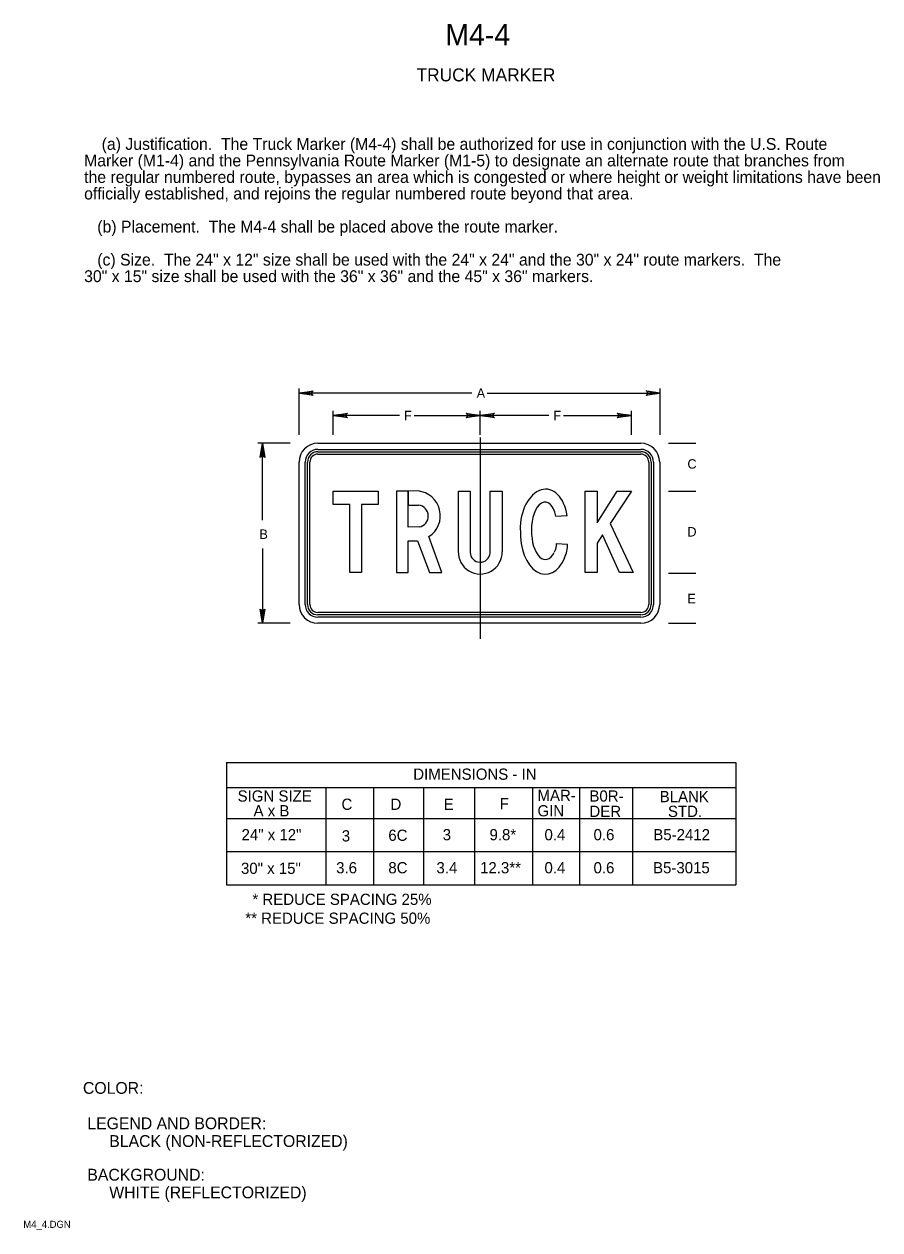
# Model space of a CAD drawing. Extents: x 0.013 to 0.194, y 0.004 to 0.259.
import ezdxf

# ---------------------------------------------------------------- set-up
doc = ezdxf.new("R2010")
doc.units = 0
for name, color, linetype in [('1', 7, 'Continuous'), ('2', 7, 'Continuous'), ('3', 7, 'Continuous')]:
    doc.layers.add(name, color=color, linetype=linetype)

# ---------------------------------------------------------------- blocks, each defined once
blk = doc.blocks.new('RARROW')
at = {"layer": '3'}
for p, q in [((-2.156, 0.28500000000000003), (-2.2665, 0.384625)), ((-2.2665, 0.384625), (0, 0)), ((0, 0), (-2.2665, -0.379125)), ((-2.156, 0.28500000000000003), (-2.075625, 0.12075)), ((0, 0), (-2.156, 0.28500000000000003)), ((-2.14975, -0.2705), (0, 0)), ((-2.075625, 0.12075), (0, 0)), ((0, 0), (-2.074, -0.108)), ((-2.2665, -0.379125), (-2.14975, -0.2705)), ((-2.074, -0.108), (-2.14975, -0.2705))]:
    blk.add_line(p, q, dxfattribs=at)

msp = doc.modelspace()

# ---------------------------------------------------------------- linework, layer by layer
at = {"layer": '2'}
for p, q in [((0.074875, 0.1705), (0.14325000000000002, 0.1705)), ((0.07087500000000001, 0.136375), (0.07087500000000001, 0.1665)), ((0.14725, 0.1665), (0.14725, 0.136375)), ((0.104625, 0.160375), (0.107125, 0.160375)), ((0.104625, 0.147625), (0.104625, 0.160375)), ((0.107125, 0.160375), (0.107125, 0.147375)), ((0.111375, 0.14725), (0.111375, 0.160375)), ((0.111375, 0.160375), (0.113875, 0.160375)), ((0.113875, 0.160375), (0.113875, 0.1475)), ((0.14325000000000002, 0.132375), (0.074875, 0.132375))]:
    msp.add_line(p, q, dxfattribs=at)
for points in [[(0.078125, 0.160375), (0.08762500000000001, 0.160375), (0.08762500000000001, 0.1575), (0.084125, 0.1575), (0.084125, 0.143125), (0.081625, 0.143125), (0.081625, 0.1575), (0.078125, 0.1575), (0.078125, 0.160375)], [(0.1315, 0.143125), (0.1315, 0.160375), (0.134, 0.160375), (0.134, 0.153625), (0.13825, 0.160375), (0.14125000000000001, 0.160375), (0.13675, 0.1535), (0.141625, 0.143125), (0.13875, 0.143125), (0.135125, 0.151125), (0.134, 0.149375), (0.134, 0.143125), (0.1315, 0.143125)]]:
    msp.add_lwpolyline(points, dxfattribs=at)
for centre, radius, start, end in [((0.074875, 0.1665), 0.004, 90, 180), ((0.14325000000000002, 0.1665), 0.004, 0, 90), ((0.1092502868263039, 0.14746159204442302), 0.004645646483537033, 177.67846944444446, 0.7742194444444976), ((0.1092502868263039, 0.14746159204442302), 0.0021456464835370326, 181.68468333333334, 355.2363583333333), ((0.074875, 0.136375), 0.004, 180, 270), ((0.14325000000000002, 0.136375), 0.004, 270, 0)]:
    msp.add_arc(centre, radius, start, end, dxfattribs=at)
at = {"layer": '3'}
for p, q in [((0.07087500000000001, 0.17225000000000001), (0.07087500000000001, 0.182125)), ((0.147375, 0.17225000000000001), (0.147375, 0.182125)), ((0.1075, 0.181125), (0.07087500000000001, 0.181125)), ((0.11075, 0.181125), (0.147375, 0.181125)), ((0.078125, 0.17225000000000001), (0.078125, 0.177375)), ((0.092125, 0.176375), (0.078125, 0.176375)), ((0.09525, 0.176375), (0.10925, 0.176375)), ((0.10925, 0.17225000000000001), (0.10925, 0.177375)), ((0.12375, 0.176375), (0.10925, 0.176375)), ((0.12687500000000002, 0.176375), (0.14125000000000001, 0.176375)), ((0.14125000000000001, 0.17225000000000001), (0.14125000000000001, 0.177375)), ((0.10925, 0.17175), (0.10925, 0.129125)), ((0.069, 0.1705), (0.062125, 0.1705)), ((0.063125, 0.15425), (0.063125, 0.1705)), ((0.074875, 0.16919999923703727), (0.14325000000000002, 0.16919999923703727)), ((0.074875, 0.16869999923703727), (0.14325000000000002, 0.16869999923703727)), ((0.149125, 0.1705), (0.154875, 0.1705)), ((0.07217500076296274, 0.136375), (0.07217500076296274, 0.1665)), ((0.07267500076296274, 0.136375), (0.07267500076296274, 0.1665)), ((0.07317500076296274, 0.136375), (0.07317500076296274, 0.1665)), ((0.074875, 0.16819999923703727), (0.14325000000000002, 0.16819999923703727)), ((0.14494999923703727, 0.1665), (0.14494999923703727, 0.136375)), ((0.14544999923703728, 0.1665), (0.14544999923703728, 0.136375)), ((0.14594999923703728, 0.1665), (0.14594999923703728, 0.136375)), ((0.094, 0.160375), (0.0915, 0.160375)), ((0.0915, 0.160375), (0.0915, 0.143125)), ((0.09607265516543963, 0.16039909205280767), (0.094, 0.160375)), ((0.094, 0.160375), (0.094, 0.15737500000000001)), ((0.094, 0.15737500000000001), (0.094, 0.160375)), ((0.149125, 0.160375), (0.154875, 0.160375)), ((0.094, 0.15737500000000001), (0.09620825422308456, 0.15739909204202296)), ((0.094, 0.15275), (0.094, 0.15737500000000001)), ((0.12762500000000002, 0.155125), (0.12525, 0.155)), ((0.12762500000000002, 0.155125), (0.12762500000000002, 0.155125)), ((0.09633325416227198, 0.15277409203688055), (0.094, 0.15275)), ((0.101125, 0.143125), (0.09839251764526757, 0.15073655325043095)), ((0.063125, 0.14825), (0.063125, 0.132375)), ((0.094, 0.143125), (0.094, 0.149875)), ((0.094, 0.149875), (0.096, 0.149875)), ((0.096, 0.149875), (0.0985, 0.143125)), ((0.12537500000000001, 0.14925), (0.12775, 0.149125)), ((0.0915, 0.143125), (0.094, 0.143125)), ((0.0985, 0.143125), (0.101125, 0.143125)), ((0.149125, 0.14300000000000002), (0.154875, 0.14300000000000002)), ((0.14325000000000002, 0.13467500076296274), (0.074875, 0.13467500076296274)), ((0.14325000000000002, 0.13417500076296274), (0.074875, 0.13417500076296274)), ((0.14325000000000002, 0.13367500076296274), (0.074875, 0.13367500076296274)), ((0.069, 0.132375), (0.062125, 0.132375)), ((0.149125, 0.132375), (0.154875, 0.132375)), ((0.0555, 0.10300000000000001), (0.0555, 0.077)), ((0.05556501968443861, 0.10293729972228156), (0.16334630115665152, 0.10293729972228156)), ((0.16334630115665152, 0.10293729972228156), (0.16334630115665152, 0.07697560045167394)), ((0.16334630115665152, 0.09757560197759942), (0.05556501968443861, 0.09757560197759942)), ((0.07652585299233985, 0.09757560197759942), (0.07652585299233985, 0.07697560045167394)), ((0.08662654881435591, 0.09757560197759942), (0.08662654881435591, 0.07697560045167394)), ((0.09726460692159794, 0.09757560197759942), (0.09726460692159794, 0.07697560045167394)), ((0.10800620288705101, 0.09757560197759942), (0.10800620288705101, 0.07697560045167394)), ((0.12031398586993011, 0.09763013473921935), (0.12031398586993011, 0.07703013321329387)), ((0.1302917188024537, 0.09757560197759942), (0.1302917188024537, 0.07697560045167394)), ((0.14150099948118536, 0.09757560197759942), (0.14150099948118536, 0.07697560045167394)), ((0.05556501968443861, 0.09107560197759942), (0.16334630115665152, 0.09107560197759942)), ((0.05556501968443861, 0.08407560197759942), (0.16334630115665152, 0.08407560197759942)), ((0.05552343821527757, 0.07697560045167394), (0.16334630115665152, 0.07697560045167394))]:
    msp.add_line(p, q, dxfattribs=at)
for centre, radius, start, end in [((0.074875, 0.1665), 0.0027, 90, 180), ((0.074875, 0.1665), 0.0022, 90, 180), ((0.14325000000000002, 0.1665), 0.0027, 0, 90), ((0.14325000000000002, 0.1665), 0.0022, 0, 90), ((0.074875, 0.1665), 0.0017000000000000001, 90, 180), ((0.14325000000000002, 0.1665), 0.0017000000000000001, 0, 90), ((0.0955364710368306, 0.15516060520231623), 0.005265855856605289, 302.8451777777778, 84.15585555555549), ((0.09591677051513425, 0.1550770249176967), 0.002340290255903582, 280.25109722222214, 82.84521666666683), ((0.12256278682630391, 0.14896159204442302), 0.002829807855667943, 329.47029444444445, 6.340191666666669), ((0.12030352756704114, 0.14926251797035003), 0.007447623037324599, 336.34308888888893, 359.12736111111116), ((0.074875, 0.136375), 0.0027, 180, 270), ((0.074875, 0.136375), 0.0022, 180, 270), ((0.074875, 0.136375), 0.0017000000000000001, 180, 270), ((0.14325000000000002, 0.136375), 0.0027, 270, 0), ((0.14325000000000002, 0.136375), 0.0017000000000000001, 270, 0), ((0.14325000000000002, 0.136375), 0.0022, 270, 0)]:
    msp.add_arc(centre, radius, start, end, dxfattribs=at)
for centre, major_axis, ratio, start_param, end_param in [((0.12275028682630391, 0.152899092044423), (0.0005900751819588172, 0.007867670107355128), 0.6355121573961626, 5.051914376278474, 8.000065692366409), ((0.12275028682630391, 0.15296159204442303), (0.0003616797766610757, 0.005063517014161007), 0.5184143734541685, 5.18183954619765, 8.061923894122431), ((0.12287528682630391, 0.151086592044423), (-0.000304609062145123, 0.008325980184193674), 0.6155431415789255, 1.4327922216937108, 4.066766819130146), ((0.12293778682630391, 0.151586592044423), (-0.0001270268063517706, 0.0057162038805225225), 0.4920223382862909, 1.4796882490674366, 3.880693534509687)]:
    msp.add_ellipse(centre, major_axis=major_axis, ratio=ratio, start_param=start_param, end_param=end_param, dxfattribs=at)

# ---------------------------------------------------------------- block references
at = {"layer": '3', "xscale": 0.0013236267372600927, "yscale": 0.001309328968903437}
for p, rotation in [((0.07087500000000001, 0.181125), 180), ((0.078125, 0.176375), 180), ((0.10925, 0.176375), 180), ((0.063125, 0.1705), 90), ((0.063125, 0.132375), -90)]:
    msp.add_blockref('RARROW', p, dxfattribs=dict(at, rotation=rotation))
for p in [(0.147375, 0.181125), (0.10925, 0.176375), (0.14125000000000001, 0.176375)]:
    msp.add_blockref('RARROW', p, dxfattribs=at)

# ---------------------------------------------------------------- texts
at = {"layer": '1'}
for s, height, p in [('M4-4', 0.0045000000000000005, (0.10187500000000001, 0.25475000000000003)), ('TRUCK MARKER', 0.00275025, (0.09575, 0.247125)), ('COLOR:', 0.0024997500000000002, (0.025125, 0.03275)), (' LEGEND AND BORDER:', 0.0024997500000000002, (0.025125, 0.02525)), ('      BLACK (NON-REFLECTORIZED)', 0.0024997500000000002, (0.025125, 0.021500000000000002)), (' BACKGROUND:', 0.0024997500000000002, (0.025125, 0.014375)), ('      WHITE (REFLECTORIZED)', 0.0024997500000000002, (0.025125, 0.010625)), ('M4_4.DGN', 0.0015, (0.0125, 0.004375))]:
    msp.add_text(s, height=height, dxfattribs=at).set_placement(p)
at = {"layer": '2'}
for s, p in [('    (a) Justification.  The Truck Marker (M4-4) shall be authorized for use in conjunction with the U.S. Route ', (0.025375, 0.232624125)), ('Marker (M1-4) and the Pennsylvania Route Marker (M1-5) to designate an alternate route that branches from ', (0.025375, 0.229124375)), ('the regular numbered route, bypasses an area which is congested or where height or weight limitations have been ', (0.025375, 0.22562462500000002)), ('officially established, and rejoins the regular numbered route beyond that area.', (0.025375, 0.222124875)), ('   (b) Placement.  The M4-4 shall be placed above the route marker.', (0.025375, 0.215125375)), ('   (c) Size.  The 24" x 12" size shall be used with the 24" x 24" and the 30" x 24" route markers.  The ', (0.025375, 0.20812587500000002)), ('30" x 15" size shall be used with the 36" x 36" and the 45" x 36" markers.', (0.025375, 0.20462612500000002))]:
    msp.add_text(s, height=0.0024997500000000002, dxfattribs=at).set_placement(p)
at = {"layer": '3'}
for s, height, p in [('A', 0.00200025, (0.1085, 0.180125)), ('F', 0.00200025, (0.093125, 0.175375)), ('F', 0.00200025, (0.12475, 0.175375)), ('C', 0.00200025, (0.153125, 0.165125)), ('B', 0.00200025, (0.0625, 0.15025)), ('D', 0.00200025, (0.153125, 0.15075)), ('E', 0.00200025, (0.153125, 0.136625)), ('DIMENSIONS - IN', 0.0023752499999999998, (0.09506659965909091, 0.09925)), ('SIGN SIZE', 0.0023752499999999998, (0.057875, 0.094625)), ('MAR-', 0.0023752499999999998, (0.121375, 0.09475)), ('B0R-', 0.0023752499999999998, (0.132375, 0.094625)), ('C', 0.0023752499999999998, (0.079875, 0.092875)), ('D', 0.0023752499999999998, (0.09025, 0.092875)), ('E', 0.0023752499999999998, (0.1015, 0.092875)), ('F', 0.0023752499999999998, (0.113375, 0.093)), ('BLANK', 0.0023752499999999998, (0.14725, 0.0945)), ('A x B', 0.0023752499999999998, (0.06125, 0.0915)), ('GIN', 0.0023752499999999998, (0.121375, 0.0915)), ('DER', 0.0023752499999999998, (0.132375, 0.091375)), ('STD.', 0.0023752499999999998, (0.149, 0.091375)), ('24" x 12"', 0.0023752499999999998, (0.0587113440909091, 0.08643737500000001)), ('3', 0.0023752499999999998, (0.07993161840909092, 0.08618737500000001)), ('6C', 0.0023752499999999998, (0.08978957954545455, 0.08631237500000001)), ('3', 0.0023752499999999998, (0.10130661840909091, 0.08643737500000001)), ('9.8*', 0.0023752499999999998, (0.11121579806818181, 0.08643737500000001)), ('0.4', 0.0023752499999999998, (0.12285699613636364, 0.08643737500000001)), ('0.6', 0.0023752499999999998, (0.13324351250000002, 0.08643737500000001)), ('B5-2412', 0.0023752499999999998, (0.14589740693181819, 0.08643737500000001)), ('30" x 15"', 0.0023752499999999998, (0.0585863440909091, 0.079312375)), ('3.6', 0.0023752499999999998, (0.0787435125, 0.079437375)), ('8C', 0.0023752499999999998, (0.08978957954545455, 0.079437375)), ('3.4', 0.0023752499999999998, (0.09998199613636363, 0.079437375)), ('12.3**', 0.0023752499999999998, (0.10921867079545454, 0.079437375)), ('0.4', 0.0023752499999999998, (0.12285699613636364, 0.079437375)), ('0.6', 0.0023752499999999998, (0.13324351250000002, 0.079437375)), ('B5-3015', 0.0023752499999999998, (0.14584882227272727, 0.079437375)), ('* REDUCE SPACING 25%', 0.0023752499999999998, (0.061, 0.07275)), ('** REDUCE SPACING 50%', 0.0023752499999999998, (0.059500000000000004, 0.06875))]:
    msp.add_text(s, height=height, dxfattribs=at).set_placement(p)

doc.saveas('drawing.dxf')
